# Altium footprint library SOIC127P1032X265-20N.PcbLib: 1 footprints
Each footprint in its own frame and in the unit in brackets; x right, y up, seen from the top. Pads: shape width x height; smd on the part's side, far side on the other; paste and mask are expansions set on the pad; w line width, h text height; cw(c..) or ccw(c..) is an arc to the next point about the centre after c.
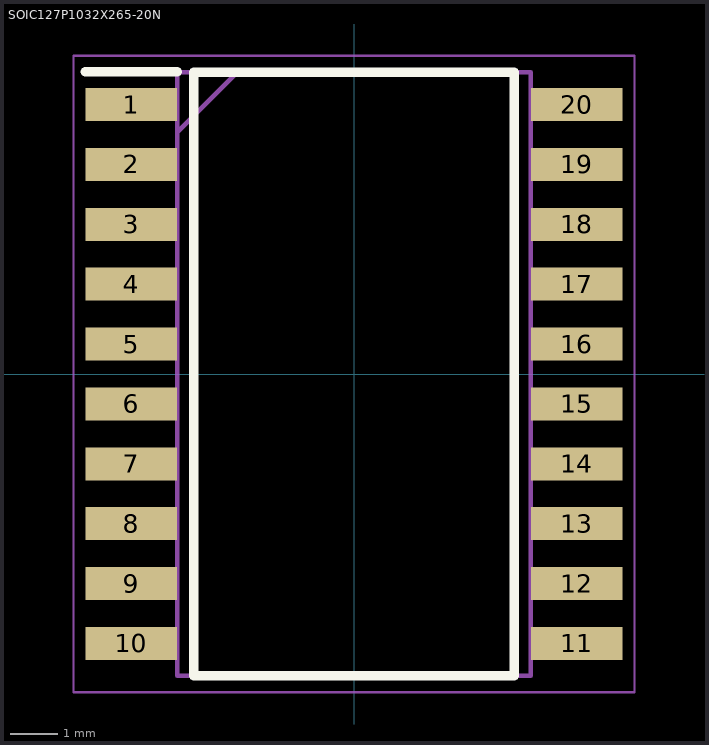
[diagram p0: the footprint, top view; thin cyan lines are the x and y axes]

## SOIC127P1032X265-20N [mm]
pads (20):
  rect 1.95x0.7 smd: 1(-4.725,5.715) 2(-4.725,4.445) 3(-4.725,3.175) 4(-4.725,1.905) 5(-4.725,0.635) 6(-4.725,-0.635) 7(-4.725,-1.905) 8(-4.725,-3.175) 9(-4.725,-4.445) 10(-4.725,-5.715) 11(4.725,-5.715) 12(4.725,-4.445) 13(4.725,-3.175) 14(4.725,-1.905) 15(4.725,-0.635) 16(4.725,0.635) 17(4.725,1.905) 18(4.725,3.175) 19(4.725,4.445) 20(4.725,5.715)
Top Overlay:
  lines w0.2: -5.7,6.415 -3.75,6.415 ; -3.4,-6.4 3.4,-6.4 3.4,6.4 -3.4,6.4 -3.4,-6.4
Mechanical 15:
  lines w0.1: -3.75,5.13 -2.48,6.4 ; -3.75,-6.4 3.75,-6.4 3.75,6.4 -3.75,6.4 -3.75,-6.4
Mechanical 20:
  lines w0.05: -5.95,-6.75 5.95,-6.75 5.95,6.75 -5.95,6.75 -5.95,-6.75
